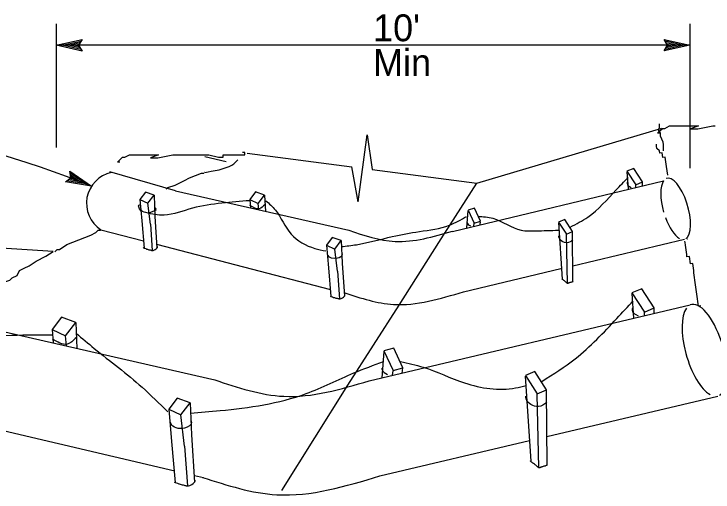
# Model space of a CAD drawing. Extents: x 6707415 to 6708768, y 1869893 to 1870831.
# Drawn here: x 6707735.5 to 6707891.3, y 1870269.7 to 1870376.4 of the extents above; entities that cross this region are included whole.
import ezdxf

# ---------------------------------------------------------------- set-up
doc = ezdxf.new("R2010")
doc.units = 0
for name, color, linetype in [('56 Stg 3 Anno', 7, 'Continuous'), ('57 Undefined', 7, 'Continuous'), ('60 Nongeo Data', 7, 'Continuous')]:
    doc.layers.add(name, color=color, linetype=linetype)

msp = doc.modelspace()

# ---------------------------------------------------------------- linework, layer by layer
at = {"layer": '56 Stg 3 Anno'}
for p, q in [((6707744.92, 1870374.22), (6707744.92, 1870346.59)), ((6707886.21, 1870374.22), (6707886.21, 1870341.97)), ((6707886.21, 1870369.41), (6707744.92, 1870369.42)), ((6707744.93, 1870369.42), (6707750.7, 1870370.68)), ((6707750.69, 1870368.11), (6707744.93, 1870369.42)), ((6707744.93, 1870369.42), (6707744.93, 1870369.42)), ((6707746.27, 1870369.42), (6707750.47, 1870370.33)), ((6707747.58, 1870369.41), (6707750.3, 1870370)), ((6707748.91, 1870369.4), (6707750.07, 1870369.66)), ((6707750.7, 1870370.68), (6707749.92, 1870369.4)), ((6707750.7, 1870370.68), (6707750.7, 1870370.68)), ((6707881.22, 1870369.42), (6707880.45, 1870370.7)), ((6707880.45, 1870370.7), (6707880.45, 1870370.7)), ((6707880.45, 1870370.7), (6707886.21, 1870369.41)), ((6707880.66, 1870370.36), (6707884.88, 1870369.42)), ((6707880.88, 1870370.02), (6707883.56, 1870369.42)), ((6707881.05, 1870369.68), (6707882.23, 1870369.42)), ((6707750.48, 1870368.46), (6707746.26, 1870369.42)), ((6707750.26, 1870368.8), (6707747.58, 1870369.41)), ((6707750.09, 1870369.14), (6707748.91, 1870369.4)), ((6707749.92, 1870369.4), (6707750.69, 1870368.11)), ((6707750.69, 1870368.11), (6707750.69, 1870368.11)), ((6707880.45, 1870368.14), (6707881.22, 1870369.42)), ((6707886.21, 1870369.41), (6707880.45, 1870368.14)), ((6707880.45, 1870368.14), (6707880.45, 1870368.14)), ((6707884.87, 1870369.41), (6707880.67, 1870368.48)), ((6707883.56, 1870369.42), (6707880.84, 1870368.82)), ((6707882.23, 1870369.42), (6707881.07, 1870369.16)), ((6707886.21, 1870369.41), (6707886.21, 1870369.41)), ((6707746.98, 1870338.94), (6707748.17, 1870339.83)), ((6707748.17, 1870339.83), (6707747.94, 1870341.31)), ((6707747.94, 1870341.31), (6707747.94, 1870341.31)), ((6707747.94, 1870341.31), (6707752.8, 1870337.97)), ((6707748.01, 1870340.92), (6707751.57, 1870338.47)), ((6707748.08, 1870340.52), (6707750.34, 1870338.96)), ((6707748.12, 1870340.14), (6707749.11, 1870339.46)), ((6707752.8, 1870337.97), (6707746.98, 1870338.94)), ((6707746.98, 1870338.94), (6707746.98, 1870338.94)), ((6707751.56, 1870338.47), (6707747.32, 1870339.17)), ((6707750.34, 1870338.96), (6707747.6, 1870339.42)), ((6707749.11, 1870339.46), (6707747.94, 1870339.65)), ((6707752.8, 1870337.97), (6707752.8, 1870337.97))]:
    msp.add_line(p, q, dxfattribs=at)
msp.add_ellipse((6707692.49, 1870326.8), major_axis=(94.95, -17.15), ratio=0.279834, start_param=0.934096, end_param=2.086505, dxfattribs=at)
at = {"layer": '60 Nongeo Data'}
for p, q in [((6707812.25, 1870334.5), (6707814.21, 1870349.45)), ((6707814.21, 1870349.45), (6707815.39, 1870341.71)), ((6707812.25, 1870334.5), (6707810.8, 1870342.3)), ((6707771.53, 1870336.96), (6707756.84, 1870341.13)), ((6707831.54, 1870327.45), (6707838.68, 1870338.66)), ((6707833.26, 1870327.86), (6707880.33, 1870339.18)), ((6707771.53, 1870336.96), (6707810.12, 1870328.11)), ((6707766.73, 1870335.95), (6707766.94, 1870331.19)), ((6707791.39, 1870335.99), (6707791.55, 1870332.34)), ((6707765.91, 1870329.52), (6707766.35, 1870323.63)), ((6707754.85, 1870328.22), (6707764.35, 1870325.76)), ((6707821.34, 1870311.42), (6707831.63, 1870327.59)), ((6707808.47, 1870325.81), (6707808.69, 1870320.79)), ((6707860.11, 1870320.2), (6707885, 1870326.11)), ((6707885.56, 1870326.22), (6707885.65, 1870326.24)), ((6707764.54, 1870324.13), (6707764.39, 1870324.32)), ((6707767.26, 1870325), (6707806.09, 1870314.93)), ((6707835.73, 1870314.42), (6707857.43, 1870319.57)), ((6707807.61, 1870319.03), (6707808.08, 1870312.84)), ((6707809.96, 1870293.53), (6707821.34, 1870311.42)), ((6707814.7, 1870294.54), (6707886.25, 1870311.46)), ((6707718.18, 1870308.99), (6707780.25, 1870294.75)), ((6707749.27, 1870307.56), (6707749.52, 1870301.77)), ((6707795.21, 1870270.09), (6707809.96, 1870293.53)), ((6707854.3, 1870282.12), (6707892.42, 1870291.13)), ((6707709.15, 1870289.03), (6707771.34, 1870274.43)), ((6707774.76, 1870289.64), (6707775.07, 1870282.46)), ((6707817.03, 1870273.32), (6707850.44, 1870281.21)), ((6707773.52, 1870279.94), (6707774.19, 1870271.07)), ((6707775.77, 1870273.38), (6707777.75, 1870272.92))]:
    msp.add_line(p, q, dxfattribs=at)
for points in [[(6707815.39, 1870341.71), (6707838.68, 1870338.66), (6707879.9, 1870350.92)], [(6707879.52, 1870349.8), (6707878.98, 1870349.8), (6707879.52, 1870350.33), (6707880.05, 1870350.86), (6707880.59, 1870350.86), (6707881.66, 1870351.4), (6707882.73, 1870351.4), (6707883.26, 1870351.4), (6707884.33, 1870351.4), (6707885.41, 1870351.4), (6707885.94, 1870351.4), (6707886.48, 1870351.4), (6707887.55, 1870351.4), (6707888.08, 1870351.4), (6707886.34, 1870350.73), (6707887.95, 1870350.73), (6707891.29, 1870351.4), (6707891.83, 1870351.4)], [(6707880.34, 1870345.86), (6707880.34, 1870347.23), (6707880.2, 1870347.78), (6707879.92, 1870348.46), (6707879.65, 1870349.15), (6707879.65, 1870349.42), (6707879.65, 1870349.7), (6707879.51, 1870350.11), (6707879.24, 1870350.25), (6707879.24, 1870350.38), (6707879.24, 1870350.52), (6707879.24, 1870350.66), (6707879.24, 1870350.79), (6707879.38, 1870351.07), (6707879.38, 1870351.2), (6707879.38, 1870351.34), (6707879.38, 1870351.48), (6707879.38, 1870351.62), (6707879.38, 1870351.75), (6707879.38, 1870351.85)], [(6707881.24, 1870340.45), (6707880.99, 1870342.32), (6707880.92, 1870342.85), (6707880.85, 1870343.38), (6707880.78, 1870343.91), (6707880.71, 1870344.44), (6707880.18, 1870344.37), (6707880.11, 1870344.9), (6707880.04, 1870345.43), (6707879.51, 1870345.35), (6707879.44, 1870345.88), (6707878.83, 1870346.34), (6707878.76, 1870346.87), (6707878.71, 1870347.31)], [(6707759.13, 1870343.33), (6707758.6, 1870343.33), (6707759.13, 1870343.86), (6707759.67, 1870344.4), (6707760.2, 1870344.4), (6707761.27, 1870344.93), (6707762.34, 1870344.93), (6707762.88, 1870344.93), (6707763.95, 1870344.93), (6707765.02, 1870344.93), (6707765.55, 1870344.93), (6707766.09, 1870344.93), (6707767.16, 1870344.93), (6707767.69, 1870344.93), (6707765.95, 1870344.26), (6707767.56, 1870344.26), (6707770.91, 1870344.93), (6707771.44, 1870344.93), (6707771.98, 1870344.93), (6707772.51, 1870344.93), (6707773.05, 1870344.93), (6707773.58, 1870344.93), (6707774.12, 1870344.93), (6707774.65, 1870344.93), (6707775.19, 1870344.93), (6707776.26, 1870344.93), (6707777.33, 1870344.93), (6707778.4, 1870344.93), (6707778.93, 1870344.93), (6707781.08, 1870344.4), (6707782.15, 1870344.4), (6707782.15, 1870344.93), (6707783.22, 1870344.93), (6707783.75, 1870344.93), (6707784.29, 1870344.93), (6707784.82, 1870344.93), (6707785.36, 1870344.93), (6707785.89, 1870344.93), (6707786.43, 1870344.93), (6707786.43, 1870344.93), (6707786.96, 1870344.93), (6707786.96, 1870345.47), (6707786.43, 1870345.47)], [(6707778.05, 1870344.55), (6707782.83, 1870343.47)], [(6707787.52, 1870345.35), (6707810.8, 1870342.3)], [(6707778.07, 1870341.01), (6707778.01, 1870341.01), (6707778.07, 1870341.01), (6707778.79, 1870341.18), (6707779.46, 1870341.29), (6707781.25, 1870341.62), (6707783.49, 1870342.35), (6707784.05, 1870342.63), (6707784.49, 1870342.96), (6707785.11, 1870343.52), (6707785.41, 1870343.86)], [(6707769.45, 1870337.3), (6707769.8, 1870337.65), (6707771.41, 1870338.18), (6707772.48, 1870338.72), (6707773.55, 1870339.25), (6707774.62, 1870339.79), (6707777.29, 1870340.86), (6707777.83, 1870340.86), (6707777.84, 1870340.86)], [(6707872.16, 1870341.18), (6707872.4, 1870337.34)], [(6707875.62, 1870338.09), (6707875.61, 1870338.92)], [(6707874.13, 1870337.74), (6707874.12, 1870338.24)], [(6707763.58, 1870334.99), (6707763.99, 1870330.2)], [(6707765.89, 1870329.52), (6707765.91, 1870329.52), (6707765.36, 1870334.17)], [(6707788.07, 1870334.98), (6707788.23, 1870333.13)], [(6707790.12, 1870332.68), (6707789.95, 1870334.12)], [(6707836.72, 1870332.55), (6707836.42, 1870328.64)], [(6707766.94, 1870331.19), (6707767.38, 1870324.18)], [(6707763.99, 1870330.2), (6707764.54, 1870324.13)], [(6707838.02, 1870329.02), (6707838.1, 1870329.68)], [(6707839.42, 1870329.35), (6707839.52, 1870330.1)], [(6707856.89, 1870329.85), (6707857.7, 1870317.24)], [(6707744.64, 1870323.34), (6707745.15, 1870323.85), (6707745.69, 1870323.85), (6707747.29, 1870324.92), (6707749.97, 1870325.99), (6707752.65, 1870327.06), (6707753.72, 1870327.59), (6707754.25, 1870328.13), (6707754.81, 1870328.13)], [(6707860.12, 1870316.66), (6707860.01, 1870327.82)], [(6707858.89, 1870316.27), (6707858.66, 1870327.2)], [(6707718.5, 1870308.92), (6707720.15, 1870310.57), (6707721.75, 1870311.1), (6707722.82, 1870311.63), (6707723.89, 1870312.17), (6707724.96, 1870312.7), (6707727.64, 1870313.77), (6707728.18, 1870313.77), (6707729.25, 1870314.31), (6707729.25, 1870314.84), (6707729.78, 1870314.84), (6707731.39, 1870315.38), (6707732.99, 1870316.45), (6707734.6, 1870316.98), (6707735.13, 1870317.51), (6707736.2, 1870318.05), (6707736.74, 1870319.12), (6707737.81, 1870319.65), (6707738.88, 1870320.19), (6707740.49, 1870321.26), (6707742.63, 1870322.32), (6707744.23, 1870323.39), (6707726.78, 1870324.51)], [(6707766.98, 1870323.83), (6707767.18, 1870323.98), (6707767.33, 1870324.13), (6707767.38, 1870324.18), (6707767.44, 1870324.23), (6707767.49, 1870324.38), (6707767.54, 1870324.38), (6707767.54, 1870324.38), (6707767.49, 1870324.38)], [(6707805.15, 1870324.8), (6707805.59, 1870319.75)], [(6707888.62, 1870311.27), (6707888.09, 1870311.2), (6707888.02, 1870311.73), (6707887.95, 1870312.26), (6707887.88, 1870312.79), (6707887.81, 1870313.32), (6707887.74, 1870313.84), (6707887.46, 1870315.96), (6707887.31, 1870317.02), (6707887.24, 1870317.55), (6707887.17, 1870318.08), (6707887.1, 1870318.61), (6707887.03, 1870319.14), (6707886.96, 1870319.67), (6707886.89, 1870320.2), (6707886.82, 1870320.73), (6707886.29, 1870320.66), (6707886.22, 1870321.19), (6707886.15, 1870321.72), (6707886.07, 1870322.25), (6707885.54, 1870322.18), (6707885.47, 1870322.71), (6707885.4, 1870323.24), (6707885.33, 1870323.77), (6707885.26, 1870324.3), (6707885.19, 1870324.83), (6707885.12, 1870325.36), (6707885.08, 1870325.68)], [(6707764.37, 1870324.18), (6707764.52, 1870324.13), (6707764.87, 1870324.03), (6707765.07, 1870323.93), (6707765.12, 1870323.93), (6707765.27, 1870323.88), (6707765.42, 1870323.83), (6707765.57, 1870323.78), (6707765.72, 1870323.78), (6707765.87, 1870323.73), (6707765.98, 1870323.68), (6707766.13, 1870323.68), (6707766.18, 1870323.63), (6707766.23, 1870323.63), (6707766.43, 1870323.63), (6707766.48, 1870323.58), (6707766.53, 1870323.63), (6707766.68, 1870323.68), (6707766.99, 1870323.83)], [(6707807.58, 1870319.04), (6707807.61, 1870319.03), (6707807.03, 1870323.93)], [(6707805.59, 1870319.75), (6707806.16, 1870313.36)], [(6707808.69, 1870320.79), (6707809.16, 1870313.42)], [(6707860.15, 1870316.68), (6707860.14, 1870316.67), (6707860.11, 1870316.65), (6707860.03, 1870316.63), (6707859.98, 1870316.61), (6707859.88, 1870316.57), (6707859.81, 1870316.54), (6707859.62, 1870316.5), (6707859.53, 1870316.48), (6707859.44, 1870316.44), (6707859.41, 1870316.43), (6707859.35, 1870316.4), (6707859.32, 1870316.4), (6707859.28, 1870316.38), (6707859.25, 1870316.38), (6707859.22, 1870316.36), (6707859.19, 1870316.35), (6707859.15, 1870316.33), (6707859.12, 1870316.31), (6707859.09, 1870316.3), (6707859.08, 1870316.29), (6707859.03, 1870316.28), (6707859.01, 1870316.27), (6707858.98, 1870316.27), (6707858.96, 1870316.27), (6707858.94, 1870316.27), (6707858.93, 1870316.27), (6707858.91, 1870316.27), (6707858.9, 1870316.26), (6707858.89, 1870316.26), (6707858.87, 1870316.26), (6707858.87, 1870316.27), (6707858.86, 1870316.28), (6707858.85, 1870316.3), (6707858.82, 1870316.34), (6707858.74, 1870316.4), (6707858.65, 1870316.49), (6707858.55, 1870316.57), (6707858.43, 1870316.65), (6707858.34, 1870316.74), (6707858.24, 1870316.82), (6707858.09, 1870316.91), (6707857.98, 1870316.99), (6707857.9, 1870317.06), (6707857.83, 1870317.13), (6707857.77, 1870317.17), (6707857.72, 1870317.23), (6707857.67, 1870317.27), (6707857.65, 1870317.28), (6707857.64, 1870317.28), (6707857.64, 1870317.29), (6707857.64, 1870317.29)], [(6707805.98, 1870313.42), (6707806.14, 1870313.37), (6707806.51, 1870313.26), (6707806.72, 1870313.15), (6707806.78, 1870313.15), (6707806.94, 1870313.1), (6707807.1, 1870313.05), (6707807.25, 1870313), (6707807.41, 1870313), (6707807.57, 1870312.94), (6707807.68, 1870312.89), (6707807.84, 1870312.89), (6707807.89, 1870312.84), (6707807.94, 1870312.84), (6707808.16, 1870312.84), (6707808.21, 1870312.78), (6707808.26, 1870312.84), (6707808.42, 1870312.89), (6707808.75, 1870313.05)], [(6707808.74, 1870313.05), (6707808.95, 1870313.21), (6707809.11, 1870313.37), (6707809.16, 1870313.42), (6707809.21, 1870313.47), (6707809.27, 1870313.63), (6707809.32, 1870313.63), (6707809.32, 1870313.63), (6707809.27, 1870313.63)], [(6707873.27, 1870314.02), (6707873.62, 1870308.53)], [(6707878.22, 1870309.6), (6707878.21, 1870310.79)], [(6707876.09, 1870309.1), (6707876.08, 1870309.81)], [(6707744.01, 1870305.96), (6707744.26, 1870303.03)], [(6707747.25, 1870302.31), (6707746.98, 1870304.59)], [(6707817.95, 1870301.1), (6707817.5, 1870295.21)], [(6707819.91, 1870295.78), (6707820.03, 1870296.77)], [(6707822.02, 1870296.27), (6707822.17, 1870297.41)], [(6707849.5, 1870295.58), (6707850.72, 1870276.58)], [(6707852.51, 1870275.11), (6707852.16, 1870291.58)], [(6707854.37, 1870275.69), (6707854.19, 1870292.51)], [(6707770.01, 1870288.19), (6707770.63, 1870280.97)], [(6707773.49, 1870279.95), (6707773.52, 1870279.94), (6707772.7, 1870286.96)], [(6707775.07, 1870282.46), (6707775.74, 1870271.89)], [(6707770.63, 1870280.97), (6707771.46, 1870271.81)], [(6707854.42, 1870275.73), (6707854.39, 1870275.72), (6707854.35, 1870275.69), (6707854.23, 1870275.65), (6707854.15, 1870275.62), (6707854.01, 1870275.56), (6707853.9, 1870275.52), (6707853.62, 1870275.45), (6707853.48, 1870275.42), (6707853.34, 1870275.37), (6707853.29, 1870275.35), (6707853.21, 1870275.31), (6707853.15, 1870275.3), (6707853.1, 1870275.27), (6707853.06, 1870275.27), (6707853, 1870275.24), (6707852.96, 1870275.23), (6707852.9, 1870275.2), (6707852.86, 1870275.17), (6707852.8, 1870275.16), (6707852.79, 1870275.14), (6707852.72, 1870275.13), (6707852.69, 1870275.11), (6707852.65, 1870275.11), (6707852.62, 1870275.1), (6707852.58, 1870275.1), (6707852.57, 1870275.1), (6707852.54, 1870275.1), (6707852.52, 1870275.09), (6707852.51, 1870275.09), (6707852.48, 1870275.09), (6707852.48, 1870275.1), (6707852.47, 1870275.13), (6707852.45, 1870275.16), (6707852.4, 1870275.21), (6707852.29, 1870275.31), (6707852.15, 1870275.44), (6707851.99, 1870275.56), (6707851.82, 1870275.69), (6707851.68, 1870275.81), (6707851.53, 1870275.94), (6707851.31, 1870276.08), (6707851.14, 1870276.19), (6707851.01, 1870276.3), (6707850.91, 1870276.4), (6707850.82, 1870276.47), (6707850.75, 1870276.56), (6707850.68, 1870276.61), (6707850.65, 1870276.62), (6707850.63, 1870276.62), (6707850.63, 1870276.64), (6707850.62, 1870276.64)], [(6707771.2, 1870271.9), (6707771.42, 1870271.82), (6707771.96, 1870271.67), (6707772.26, 1870271.52), (6707772.33, 1870271.52), (6707772.56, 1870271.45), (6707772.79, 1870271.37), (6707773.02, 1870271.29), (6707773.25, 1870271.29), (6707773.47, 1870271.22), (6707773.62, 1870271.14), (6707773.85, 1870271.14), (6707773.93, 1870271.07), (6707774, 1870271.07), (6707774.31, 1870271.07), (6707774.38, 1870270.99), (6707774.46, 1870271.07), (6707774.69, 1870271.14), (6707775.16, 1870271.37)], [(6707775.14, 1870271.37), (6707775.44, 1870271.6), (6707775.67, 1870271.82), (6707775.75, 1870271.9), (6707775.82, 1870271.98), (6707775.9, 1870272.2), (6707775.98, 1870272.2), (6707775.98, 1870272.2), (6707775.9, 1870272.2)]]:
    msp.add_lwpolyline(points, dxfattribs=at)
for points in [[(6707872.16, 1870341.28), (6707874.1, 1870338.28), (6707875.61, 1870338.95), (6707873.7, 1870341.93)], [(6707788.07, 1870334.98), (6707789.95, 1870334.12), (6707791.39, 1870335.99), (6707789.37, 1870336.71)], [(6707763.58, 1870334.99), (6707765.36, 1870334.17), (6707766.73, 1870335.95), (6707764.81, 1870336.64)], [(6707836.74, 1870332.64), (6707838.09, 1870329.72), (6707839.53, 1870330.13), (6707838.19, 1870333.03)], [(6707856.9, 1870329.94), (6707858.65, 1870327.23), (6707860.01, 1870327.84), (6707858.29, 1870330.53)], [(6707805.15, 1870324.8), (6707807.03, 1870323.93), (6707808.47, 1870325.81), (6707806.45, 1870326.53)], [(6707873.28, 1870314.16), (6707876.05, 1870309.87), (6707878.22, 1870310.83), (6707875.48, 1870315.09)], [(6707744.01, 1870305.96), (6707746.98, 1870304.59), (6707749.27, 1870307.56), (6707746.07, 1870308.71)], [(6707817.98, 1870301.23), (6707820.02, 1870296.83), (6707822.19, 1870297.45), (6707820.17, 1870301.82)], [(6707849.51, 1870295.71), (6707852.14, 1870291.63), (6707854.2, 1870292.55), (6707851.6, 1870296.6)], [(6707770.01, 1870288.19), (6707772.7, 1870286.96), (6707774.76, 1870289.64), (6707771.87, 1870290.67)]]:
    msp.add_lwpolyline(points, close=True, dxfattribs=at)
msp.add_arc((6707758.76, 1870334.13), 7.09, 102.7086, 236.5226, dxfattribs=at)
for centre, major_axis, start_param, end_param in [((6707883.01, 1870332.91), (-1.99, 6.8), 3.24529, 6.331966), ((6707883.01, 1870332.91), (-1.99, 6.8), 0.295282, 1.570773), ((6707883.01, 1870332.91), (-1.99, 6.8), 1.742227, 2.754116), ((6707889.43, 1870301.33), (-2.99, 10.2), 3.24529, 6.331966), ((6707889.43, 1870301.33), (-2.99, 10.2), 0.295282, 2.754116)]:
    msp.add_ellipse(centre, major_axis=major_axis, ratio=0.392736, start_param=start_param, end_param=end_param, dxfattribs=at)
for points in [[(6707859.52, 1870328.84), (6707863.44, 1870331.08), (6707869.75, 1870337.11), (6707872.42, 1870339.91)], [(6707872.24, 1870338.89), (6707872.17, 1870338.56), (6707873.1, 1870337.7)], [(6707788.04, 1870334.72), (6707781.87, 1870334.16), (6707775.28, 1870333.04), (6707768.97, 1870331.5), (6707764.91, 1870332.06), (6707763.51, 1870332.9), (6707763.37, 1870333.74), (6707763.79, 1870333.88)], [(6707791.48, 1870333.88), (6707790.17, 1870332.92), (6707788.12, 1870333.66)], [(6707791.68, 1870334.72), (6707793.78, 1870332.62), (6707797.29, 1870327.29), (6707802.61, 1870324.07), (6707805, 1870323.51)], [(6707765.79, 1870332.09), (6707767.15, 1870332.96), (6707766.93, 1870333.12)], [(6707808.5, 1870324.49), (6707811.86, 1870324.91), (6707819.85, 1870326.73), (6707825.88, 1870327.85), (6707832.61, 1870329.26), (6707836.39, 1870331.22)], [(6707838.92, 1870331.22), (6707842.28, 1870330.8), (6707848.59, 1870328.13), (6707851.81, 1870327.99), (6707856.86, 1870328.13)], [(6707836.44, 1870330.08), (6707836.47, 1870329.83), (6707837.27, 1870329.12)], [(6707810.12, 1870328.11), (6707820.48, 1870325.63), (6707833.26, 1870327.96)], [(6707860.09, 1870325.93), (6707858.82, 1870325.33), (6707857.03, 1870326.47), (6707856.96, 1870326.89)], [(6707808.63, 1870323.01), (6707808.69, 1870322.78), (6707807.6, 1870321.87), (6707805.49, 1870322.55), (6707805.38, 1870322.95)], [(6707809.26, 1870314.14), (6707820.1, 1870311.57), (6707835.73, 1870314.42)], [(6707853.21, 1870294.41), (6707860.64, 1870299.46), (6707869.89, 1870308.43), (6707873.54, 1870312.36)], [(6707873.39, 1870310.75), (6707873.29, 1870310.28), (6707874.63, 1870309.04)], [(6707744.12, 1870304.74), (6707737.51, 1870304.68), (6707727.34, 1870304.26), (6707714.16, 1870302.03), (6707706.88, 1870300.11), (6707703.75, 1870300.71), (6707703.27, 1870301.73), (6707703.63, 1870302.45)], [(6707749.42, 1870304.22), (6707747.34, 1870302.69), (6707744.08, 1870303.86)], [(6707749.35, 1870305.14), (6707753.41, 1870301.77), (6707764.07, 1870293.08), (6707769.81, 1870287.61)], [(6707774.86, 1870287.33), (6707781.45, 1870287.89), (6707800.65, 1870291.68), (6707811.3, 1870296.3), (6707817.89, 1870298.83)], [(6707821.68, 1870298.83), (6707826.72, 1870297.57), (6707835.97, 1870294.06), (6707847.33, 1870292.94), (6707849.71, 1870293.5)], [(6707817.53, 1870297.37), (6707817.57, 1870297), (6707818.79, 1870295.92)], [(6707780.25, 1870294.75), (6707795.66, 1870291.07), (6707814.7, 1870294.54)], [(6707854.31, 1870289.67), (6707852.41, 1870288.77), (6707849.7, 1870290.49), (6707849.61, 1870291.12)], [(6707774.98, 1870285.63), (6707775.07, 1870285.31), (6707773.52, 1870284), (6707770.49, 1870284.98), (6707770.33, 1870285.55)], [(6707777.57, 1870272.96), (6707794.09, 1870269.11), (6707817.1, 1870273.3)]]:
    msp.add_spline(points, degree=3, dxfattribs=at)

# ---------------------------------------------------------------- texts
at = {"layer": '57 Undefined'}
for s, p in [("10'", (6707815.56, 1870370.3)), ('Min', (6707815.56, 1870362.54))]:
    msp.add_text(s, height=6, dxfattribs=at).set_placement(p)

doc.saveas('drawing.dxf')
